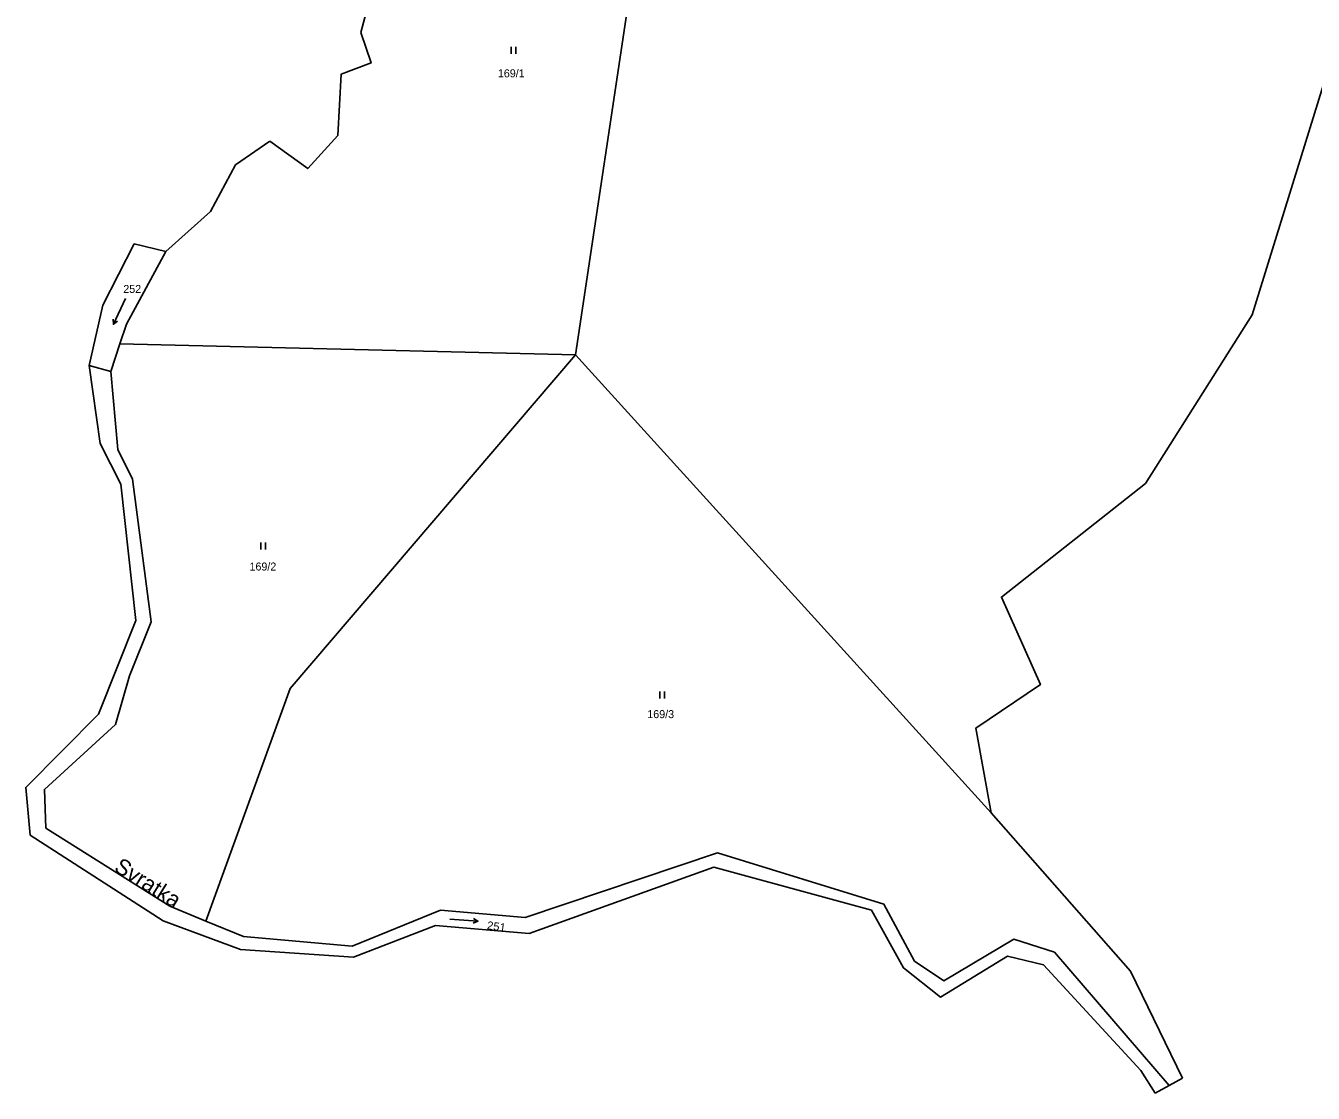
# Model space of a CAD drawing. Extents: x -632162 to -629607, y -1101195 to -1098670.
# Drawn here: x -631488.4 to -631215, y -1101194.6 to -1100967.9 of the extents above; entities that cross this region are included whole.
import ezdxf
from ezdxf.enums import TextEntityAlignment as Align

# ---------------------------------------------------------------- set-up
doc = ezdxf.new("R2010")
doc.units = 0
doc.header["$LTSCALE"] = 0.68
for name, color, linetype, lineweight in [('1', 7, 'Continuous', 25), ('3', 7, 'Continuous', 25), ('7', 7, 'Continuous', 13)]:
    doc.layers.add(name, color=color, linetype=linetype, lineweight=lineweight)
doc.layers.add('2', color=7, linetype='Continuous')

msp = doc.modelspace()

# ---------------------------------------------------------------- linework, layer by layer
at = {"layer": '1'}
for p, q in [((-631458.66, -1101015.83), (-631465.41, -1101014.25)), ((-631470.39, -1101041.34), (-631474.93, -1101040.08)), ((-631371.68, -1101037.79), (-631283.42, -1101135.03)), ((-631248.57, -1101194.58), (-631251.61, -1101189.74)), ((-631245.64, -1101192.95), (-631248.57, -1101194.58)), ((-631242.79, -1101191.38), (-631245.64, -1101192.95))]:
    msp.add_line(p, q, dxfattribs=at)
for points in [[(-630733.19, -1100619.24), (-630786.89, -1100667.53), (-630844.3, -1100705.78), (-630883.66, -1100738.94), (-630999.12, -1100794.91), (-631077.07, -1100803.32), (-631098.35, -1100847.39), (-631140.84, -1100885.1), (-631145.48, -1100937.86), (-631207.96, -1100964.63), (-631227.95, -1101029.28), (-631250.62, -1101065.11), (-631281.22, -1101089.22), (-631272.94, -1101107.79), (-631286.65, -1101117.05), (-631283.42, -1101135.03)], [(-631371.68, -1101037.79), (-631359.28, -1100955.19), (-631352.13, -1100838.04), (-631360.63, -1100832.55)], [(-631417.92, -1100907.83), (-631409.79, -1100912.6), (-631400.16, -1100922.16), (-631395.13, -1100934.69), (-631395.94, -1100940.99), (-631402.63, -1100951.59), (-631414.77, -1100960.03), (-631417.24, -1100969.35), (-631415.08, -1100975.79), (-631421.47, -1100978.21), (-631422.18, -1100991.22), (-631428.53, -1100998.24), (-631436.59, -1100992.4)], [(-631436.59, -1100992.4), (-631443.91, -1100997.47), (-631449.22, -1101007.33), (-631458.66, -1101015.83)], [(-631465.41, -1101014.25), (-631472.07, -1101027.25), (-631474.93, -1101040.08)], [(-631458.66, -1101015.83), (-631467, -1101031.25), (-631468.43, -1101035.49), (-631371.68, -1101037.79)], [(-631450.18, -1101158.03), (-631457.85, -1101154.87), (-631484.17, -1101138.26), (-631484.47, -1101130.07), (-631469.34, -1101116.25), (-631466.38, -1101105.92), (-631461.77, -1101094.45), (-631465.73, -1101064.18), (-631468.91, -1101057.86), (-631470.39, -1101041.34), (-631468.43, -1101035.49)], [(-631251.61, -1101189.74), (-631272.33, -1101167.34), (-631279.96, -1101165.48), (-631294.2, -1101174.17), (-631302.02, -1101167.98), (-631308.85, -1101155.74), (-631342.34, -1101146.57), (-631381.55, -1101160.65), (-631401.4, -1101158.94), (-631418.8, -1101165.67), (-631442.8, -1101164.03), (-631459.25, -1101157.99), (-631487.46, -1101139.75), (-631488.43, -1101129.63), (-631472.97, -1101114.08), (-631465.05, -1101094.21), (-631468.26, -1101065.25), (-631472.64, -1101056.65), (-631474.93, -1101040.08)], [(-631450.18, -1101158.03), (-631432.3, -1101108.64), (-631371.68, -1101037.79)], [(-631283.42, -1101135.03), (-631253.84, -1101168.69), (-631242.79, -1101191.38)], [(-631245.64, -1101192.95), (-631269.98, -1101164.62), (-631278.6, -1101161.83), (-631293.47, -1101170.7), (-631299.69, -1101166.52), (-631306.17, -1101154.43), (-631341.55, -1101143.55), (-631382.39, -1101157.29), (-631400.33, -1101155.73), (-631419.1, -1101163.35), (-631442.19, -1101161.32), (-631450.18, -1101158.03)]]:
    msp.add_lwpolyline(points, dxfattribs=at)
at = {"layer": '3'}
for p, q in [((-631385.321, -1100973.9), (-631385.321, -1100972.4)), ((-631384.32, -1100973.9), (-631384.32, -1100972.4)), ((-631469.803, -1101031.291), (-631469.844, -1101030.193)), ((-631438.491, -1101079.14), (-631438.491, -1101077.64)), ((-631437.49, -1101079.14), (-631437.49, -1101077.64)), ((-631353.771, -1101110.78), (-631353.771, -1101109.28)), ((-631352.77, -1101110.78), (-631352.77, -1101109.28)), ((-631392.391, -1101158.019), (-631393.401, -1101158.451))]:
    msp.add_line(p, q, dxfattribs=at)
for points in [[(-631467.267, -1101025.853), (-631469.803, -1101031.291), (-631468.935, -1101030.617)], [(-631398.376, -1101157.6), (-631392.391, -1101158.019), (-631393.331, -1101157.451)]]:
    msp.add_lwpolyline(points, dxfattribs=at)

# ---------------------------------------------------------------- texts
at = {"layer": '2'}
for s, p in [('169/1', (-631385.32, -1100978.87)), ('252', (-631465.819, -1101024.65)), ('169/2', (-631438.07, -1101083.59)), ('169/3', (-631353.59, -1101114.93))]:
    msp.add_text(s, height=1.7, dxfattribs=at).set_placement(p, align=Align.CENTER)
at = {"layer": '2', "width": 1.05}
msp.add_text('251', height=1.7, rotation=352, dxfattribs=at).set_placement((-631388.5883, -1101160.002), align=Align.CENTER)
at = {"layer": '7'}
msp.add_text('Svratka', height=3.4, rotation=328, dxfattribs=at).set_placement((-631463.3599, -1101151.3471), align=Align.CENTER)

doc.saveas('drawing.dxf')
